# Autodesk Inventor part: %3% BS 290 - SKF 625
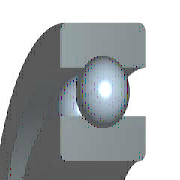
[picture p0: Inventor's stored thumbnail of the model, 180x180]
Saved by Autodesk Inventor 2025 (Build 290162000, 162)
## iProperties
Created: 2024-01
Part Number: %3% BS 290 - SKF 625
Material: Acciaio, Dolce
Description: Cuscinetti a sfere a fila singola
Document SubType Name: Modeling
Standard: BS 290
Designer: R5800u
Standards Organization: BSI
Language: it-IT
Size Designation: SKF 625
Categories: <MemberInstance><Categories><Category DisplayName="Parti albero" InternalName="7f7aeb1f-a693-4053-b835-cee3144e0d98" Mnemonic="SHFT"><Category DisplayName="Cusc
Density: 7.85 g/cm^3
Appearance: Semilucidato
IsCustomPart: 0
Author: R5800u
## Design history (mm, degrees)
node "WorkPoint1"
node "WorkAxis1"
node "WorkPlane3"
node "WorkPlane4"
node "WorkPoint2"
pattern_circular "Seriepolare1" dims "d17" = 51.72727 (= msp_pocet), angle "d19" = 360 deg
body "Solid1"
node "Schizzo1"
revolve "Rivoluzione1" stored, may be unused: angle "d6" = 360 deg
revolve "Rivoluzione2" stored, may be unused: angle "d10" = 360 deg
node "Schizzo4"
revolve "Rivoluzione3" stored, may be unused: angle "d16" = 360 deg
fillet "Raccordo1" dims "d20" = 0.3 (= r)
sketch "Schizzo2"
  geometry: L1 (2.5, 5)-(8, 5); L2 (2.5, 0)-(2.5, 5); L3 (8, 0)-(2.5, 0); L4 (8, 5)-(8, 0); L5 (0, 0)-(0, 20); L6 (0, 0)-(0, 20); L7 (-7.2, 0)-(43.2, 0) reference
  constraints: 12 end point, 3 vertical, 2 horizontal, 1 collinear, 1 other
  dimensions: "d1" = 5 vertical distance of L1.start L5 (= Diam); "d3" = 16 diameter of L1.end L5 (= DD); "d5" = 5 distance of L2.start L1.start (= msp_mdtd2)
sketch "Schizzo3"
  geometry: L1 (6.24, 5)-(6.24, 3.82); L2 (4.26, 5)-(6.24, 5); L3 (4.26, 3.82)-(4.26, 5); L4 (4.26, 0)-(4.26, 1.18); L5 (6.24, 0)-(4.26, 0); L6 (6.24, 1.18)-(6.24, 0); L7 (8, 0)-(-8, 0) reference; L8 (8, 5)-(-8, 5) reference; L9 (0, -42.29)-(0, 61.29); L10 (0, 82.007)-(0, -63.007) reference; A1 r 1.65 centre (5.25, 2.5) between (6.24, 1.18) and (6.24, 3.82); A2 r 1.65 centre (5.25, 2.5) between (4.26, 3.82) and (4.26, 1.18)
  constraints: 14 end point, 4 collinear, 4 point on circle, 4 vertical, 2 centre point, 2 concentric, 2 horizontal, 2 point on line
  dimensions: "d9" = 3.3 diameter of A1 (= msp_mdtd6); "d21" = 4.26 distance between parallel lines of L9 L4 (= 0.5 x msp_d1); "d22" = 5.25 distance from line of L9 A1.centre (= 0.5 x msp_ds); "d23" = 6.24 distance between parallel lines of L9 L6 (= 0.5 x msp_dd1)
sketch "Schizzo5"
  geometry: L1 (5.25, 0.85)-(5.25, 4.15); L2 (6.24, 0)-(-6.24, 0) reference; L3 (5.25, 0.85)-(5.25, 4.15); A1 r 1.65 centre (5.25, 2.5) between (5.25, 0.85) and (5.25, 4.15); A2 r 1.65 centre (5.25, 2.5) between (6.24, 1.18) and (6.24, 3.82) reference
  constraints: 4 end point, 2 point on circle, 1 centre point, 1 concentric, 1 vertical
  dimensions: "d13" = 0 horizontal distance of A1.centre L1.start; "d15" = 3.3001 diameter of A1 (computed from msp_mdtd6)
other parameters: "Diam" = 5 [user parameter; used in 3 equation terms], "DD" = 16 [user parameter; used in 3 equation terms], "B" = 5 [user parameter; used in 1 equation term], "r" = 0.3 [user parameter; used in 1 equation term], "msp_ds" = 10.5 (= 0.5 x Diam + 0.5 x DD) [user parameter; used in 5 equation terms], "msp_d0" = 3.3 (= -0.3 x Diam + 0.3 x DD) [user parameter; used in 4 equation terms], "msp_d1" = 8.52 (= msp_ds - 0.6 x msp_d0) [user parameter; used in 1 equation term], "msp_dd1" = 12.48 (= msp_ds + 0.6 x msp_d0) [user parameter; used in 1 equation term], "msp_pom" = 15.75 (= 1.5 x msp_ds) [user parameter; used in 1 equation term], "msp_mdtd2" = 5 (= B) [user parameter; used in 3 equation terms], "msp_mdtd4" = 10.5 (= msp_ds) [user parameter], "msp_mdtd6" = 3.3 (= msp_d0) [user parameter; used in 2 equation terms], "msp_mdtd7" = 2.5 (= 0.5 x msp_mdtd2) [user parameter], "msp_pocet" = 51.72727 (computed from msp_d0, msp_pom) [user parameter; used in 1 equation term], "d2" = 72 (derived), "d4" = 19 (derived), "d7" = 0, "d8" = 15.6 (derived), "d11" = -5 (computed from msp_mdtd2), "d12" = 0 (derived), "d14" = 15.6001 (derived), "d26" = 0, "d27" = 0, "d28" = 0, "d29" = 0, "d30" = 0
